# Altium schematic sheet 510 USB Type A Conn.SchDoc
size Letter; Organization: Toradex Solutions Inc.; Address1: 6415 Northwest Drive; Address2: Mississauga, ON, L4V 1X1; Address3: Canada
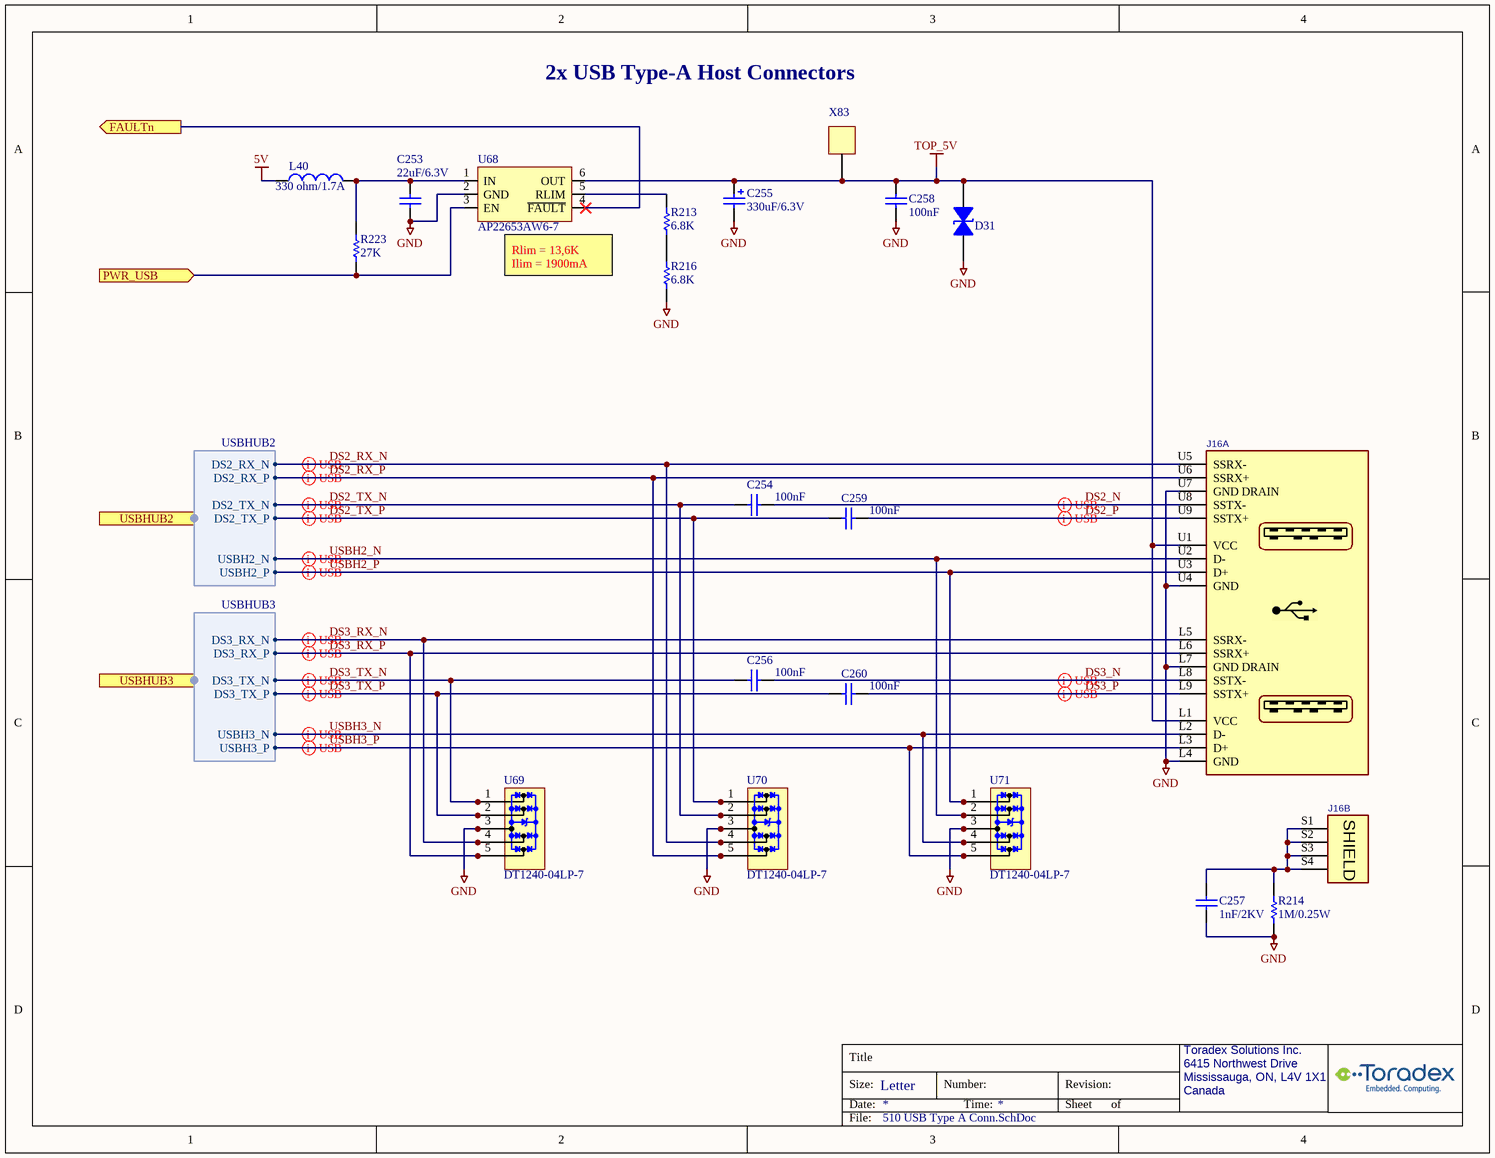
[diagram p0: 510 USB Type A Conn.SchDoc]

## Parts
C253  22uF/6.3V  [C0402_CAPC1005L]
C254  100nF  [C0402_CAPC1005L]
C255  330uF/6.3V  [CAN-SMD-D630]
C256  100nF  [C0402_CAPC1005L]
C257  value 1nF/2KV  [C/1206]  (hidden comment: 0567-Cap-1206-1nF/2KV)
C258  100nF  [C0402_CAPC1005L]
C259  100nF  [C0402_CAPC1005L]
C260  100nF  [C0402_CAPC1005L]
D31  D5V0L1B2S9-7  [SOD923_DIO]  (value not drawn)
J16  GSB4112312HR  [T_AMPHENOL_ GSB311231HR]  (value not drawn)  (parts A,B of 2)
L40  value 330 ohm/1.7A  [INDC1608x095]  (hidden comment: 0405-Fer-0603-330ohm/1.7A)
R213  value 6.8K  [R/0603]  (hidden comment: 0687-Res-0603-6.8K)
R214  value 1M/0.25W  [R/1206]  (hidden comment: 1860-Res-1206-1M-5%-0.25W)
R216  value 6.8K  [R/0603]  (hidden comment: 0687-Res-0603-6.8K)
R223  value 27K  [R0402_RESC1005L]  (hidden comment: 1538-Res-0402-27k)
U68  AP22653AW6-7  [sot23-6]
U69  DT1240-04LP-7  [10-UFDFN]
U70  DT1240-04LP-7  [10-UFDFN]
U71  DT1240-04LP-7  [10-UFDFN]
X83  000-TestPoint  [TestPoint_1]  (value not drawn)

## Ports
FAULTn (out), PWR_USB (in), USBHUB2 (harness USBHUB2), USBHUB3 (harness USBHUB3)

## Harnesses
USBHUB2: USBH2_N, USBH2_P, DS2_TX_N, DS2_TX_P, DS2_RX_N, DS2_RX_P
USBHUB3: USBH3_N, USBH3_P, DS3_TX_N, DS3_TX_P, DS3_RX_N, DS3_RX_P

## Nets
5V: L40.1
GND: C253.1 C255.2 C257.1 C258.1 D31.1 J16.L4(GND) J16.L7(GND_DRAIN) J16.U4(GND) J16.U7(GND_DRAIN) R214.2 R216.1 U68.2(GND) U69.3(GND) U69.8(GND) U70.3(GND) U70.8(GND) U71.3(GND) U71.8(GND)
TOP_5V: C255.1 C258.2 D31.2 J16.L1(VCC) J16.U1(VCC) U68.6(OUT) X83.1
DS2_N: C254.1 J16.U8(SSTX-)
DS2_P: C259.1 J16.U9(SSTX+)
DS2_RX_N: J16.U5(SSRX-) U70.4(IO3) U70.7(NC) ; port USBHUB2.DS2_RX_N
DS2_RX_P: J16.U6(SSRX+) U70.5(IO4) U70.6(NC) ; port USBHUB2.DS2_RX_P
DS2_TX_N: C254.2 U70.2(IO2) U70.9(NC) ; port USBHUB2.DS2_TX_N
DS2_TX_P: C259.2 U70.1(IO1) U70.10(NC) ; port USBHUB2.DS2_TX_P
DS3_N: C256.1 J16.L8(SSTX-)
DS3_P: C260.1 J16.L9(SSTX+)
DS3_RX_N: J16.L5(SSRX-) U69.4(IO3) U69.7(NC) ; port USBHUB3.DS3_RX_N
DS3_RX_P: J16.L6(SSRX+) U69.5(IO4) U69.6(NC) ; port USBHUB3.DS3_RX_P
DS3_TX_N: C256.2 U69.1(IO1) U69.10(NC) ; port USBHUB3.DS3_TX_N
DS3_TX_P: C260.2 U69.2(IO2) U69.9(NC) ; port USBHUB3.DS3_TX_P
FAULTn: U68.4(~{FAULT}) ; port FAULTn
PWR_USB: R223.1 U68.3(EN) ; port PWR_USB
USBH2_N: J16.U2(D-) U71.2(IO2) U71.9(NC) ; port USBHUB2.USBH2_N
USBH2_P: J16.U3(D+) U71.1(IO1) U71.10(NC) ; port USBHUB2.USBH2_P
USBH3_N: J16.L2(D-) U71.4(IO3) U71.7(NC) ; port USBHUB3.USBH3_N
USBH3_P: J16.L3(D+) U71.5(IO4) U71.6(NC) ; port USBHUB3.USBH3_P
NetC253_2: C253.2 L40.2 R223.2 U68.1(IN)
NetC257_2: C257.2 J16.S1(SHIELD) J16.S2(SHIELD) J16.S3(SHIELD) J16.S4(SHIELD) R214.1
NetR213_1: R213.1 R216.2
NetR213_2: R213.2 U68.5(RLIM)

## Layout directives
differential pair; differential pair class USBH2; differential pair class USB: DS2_N, DS2_P, DS2_RX_N, DS2_RX_P, DS2_TX_N, DS2_TX_P, USBH2_N, USBH2_P
differential pair; differential pair class USBH3; differential pair class USB: DS3_N, DS3_P, DS3_RX_N, DS3_RX_P, DS3_TX_N, DS3_TX_P, USBH3_N, USBH3_P

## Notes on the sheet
- 2x USB Type-A Host Connectors
- (near U68) Rlim = 13,6K
  Ilim = 1900mA

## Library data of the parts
C253 = 2404-Cap-0402-22uF/6.3V: (-55 to 85 DegC) CAP CER 22UF 6.3V 20% X5R 0402; MfrNo: GRM155R60J226ME11D; Mfr: Murata; PN: 2404
C254 C256 C258-C260 = 1566-Cap-0402-100nF/50V: (-55 to 125 DegC AEC) Cap Ceramic 0.1uF 50V X7R 10% 0402; MfrNo: GRT155R71H104KE01D; Mfr: Murata; Alt: CL05B104KB54PNC,GCM155R71H104ME02D,GCM155R71H104KE02D,GCM155R71H104KE02J; PN: 1566
C255 = 2241-Cap-6.6x6.6-330uF/6.3V: (-55 to 105 DegC) CAP ALUM POLY 33UF 6.3V 20% SMD 10mohm 6.6x6.6x6.1mm Ir:3.9A (100kHz); MfrNo: APXF6R3ARA331MF61G; Mfr: United Chemi-Con; PN: 2241
C257 = 0567-Cap-1206-1nF/2KV: CAP CER 1000PF 2KV X7R 1206; Mfr: Johanson Dielectrics Inc.; MfrNo: 202R18W102KV4E; PN: 567; Alt: 478-2956-1-ND; Alt2: 399-4819-1-ND
D31 = 1655-D5V0L1B2S9-7: (-65 to 155 DegC) TVS DIODE Vwm:5V Vcl:14V@6A SOD-923; Mfr: Diodes; PN: 1655
J16 = 1820-Conn-USB3-2x-RA: (-40 to 85 DegC) Conn USB 3.1 Type A R/A TH; Mfr: Amphenol Commercial; PN: 1820
L40 = 0405-Fer-0603-330ohm/1.7A: (-55 to 125 DegC) FERRITE BEAD 330 OHM 0603 1.7A 80mohm, typ 48mohm; Mfr: TDK Corporation; MfrNo: MPZ1608S331ATA00; PN: 405; TR: 445-5221-2-ND; DR: 445-5221-6-ND; DR2: 810-MPZ1608S331ATA00
R213 R216 = 0687-Res-0603-6.8K: RES SMD 6.8K OHM 1% 1/10W 0603; Mfr: Yageo; MfrNo: RC0603FR-076K8L; PN: 687; TR: 311-6.80KHRTR-ND
R214 = 1860-Res-1206-1M-5%-0.25W: (-55 to 155 DegC) RES SMD 1M OHM 5% 0.25W 10ppm 1206; Mfr: TE Connectivity; MfrNo: CRGCQ1206J1M0; PN: 1860; Alt: RMCF1206JT1M00, RMCF1206JG1M00, CR1206-JW-105ELF
R223 = 1538-Res-0402-27k: (-55 to 155 DegC AEC) RES 27K OHM 1% 1/16W 100ppm 0402; Mfr: Stackpole Electronics; MfrNo: RMCF0402FT27K0; PN: 1538; Alt: AC0402FR-0727KL,CRGCQ0402F27K
U68 = 1475-AP22653: (-40 to 85 DegC) IC PWR SWITCH 3-5.5V EN-Active-High ENth:1.5V With-Discharge 65mohm typ ADJ 0.1-2.1A 6SSOP; Mfr: Diodes; PN: 1475; Note: Similar: BD2222G, BD2242G, TPS25221, TPS2553, RT9728A, RT9728B, RT9728C, AP2553, MIC2009YM6, MIC2019YM6, MIC2009A-1YM6,MIC2019A-1YM6
U69-U71 = 1657-DT1240-04LP-7: (-55 to 85 DegC) IC TVS DIODE 4ch Vrm:5.5V Vcl:11V@5.5A 10-UFDFN 0.5mm; Mfr: Diodes; PN: 1657
X83 = 000-TestPoint: Note: this is PCB footprint only, no parts to buy or assemble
